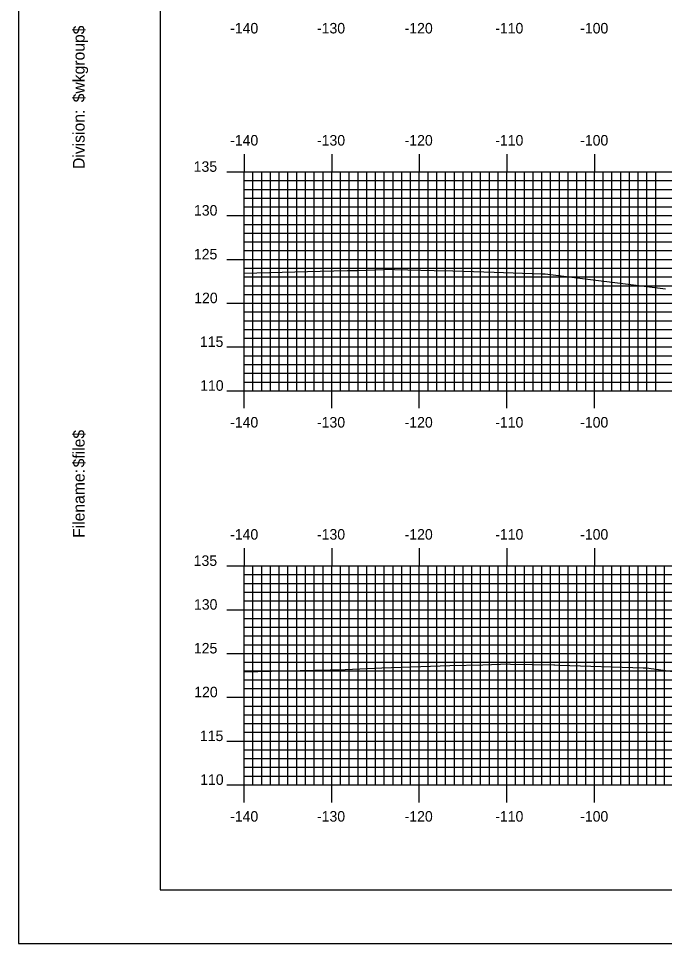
# Model space of a CAD drawing. Extents: x 843356 to 843699, y 363538 to 363758.
# Drawn here: x 843355.6 to 843429.4, y 363537.6 to 363643.2 of the extents above; entities that cross this region are included whole.
import ezdxf

# ---------------------------------------------------------------- set-up
doc = ezdxf.new("R2010")
doc.units = 0
for name, color, linetype in [('BORDER', 7, 'Continuous'), ('H_V ANNOTATION', 7, 'Continuous'), ('M_Roadway_Centerline', 7, 'Continuous'), ('MAJOR', 7, 'Continuous'), ('MINOR', 7, 'Continuous'), ('PLOT BOUNDARY', 7, 'Continuous'), ('S_Roadway_Centerline', 7, 'Continuous')]:
    doc.layers.add(name, color=color, linetype=linetype)

msp = doc.modelspace()

# ---------------------------------------------------------------- linework, layer by layer
at = {"layer": 'BORDER'}
msp.add_lwpolyline([(843371.82, 363543.72), (843691.82, 363543.72), (843691.82, 363753.72), (843371.82, 363753.72)], close=True, dxfattribs=at)
at = {"layer": 'MAJOR'}
for p, q in [((843381.42, 363627.73), (843381.42, 363625.72)), ((843391.42, 363627.73), (843391.42, 363625.72)), ((843401.42, 363627.73), (843401.42, 363625.72)), ((843411.42, 363627.73), (843411.42, 363625.72)), ((843421.42, 363627.73), (843421.42, 363625.72)), ((843379.42, 363625.72), (843381.42, 363625.72)), ((843381.42, 363625.72), (843661.42, 363625.72)), ((843381.42, 363600.72), (843381.42, 363625.72)), ((843381.42, 363600.72), (843381.42, 363625.72)), ((843381.42, 363625.72), (843661.42, 363625.72)), ((843391.42, 363600.72), (843391.42, 363625.72)), ((843401.42, 363600.72), (843401.42, 363625.72)), ((843411.42, 363600.72), (843411.42, 363625.72)), ((843421.42, 363600.72), (843421.42, 363625.72)), ((843379.42, 363620.72), (843381.42, 363620.72)), ((843381.42, 363620.72), (843661.42, 363620.72)), ((843379.42, 363615.72), (843381.42, 363615.72)), ((843381.42, 363615.72), (843661.42, 363615.72)), ((843379.42, 363610.72), (843381.42, 363610.72)), ((843381.42, 363610.72), (843661.42, 363610.72)), ((843379.42, 363605.72), (843381.42, 363605.72)), ((843381.42, 363605.72), (843661.42, 363605.72)), ((843379.42, 363600.72), (843381.42, 363600.72)), ((843381.42, 363600.72), (843661.42, 363600.72)), ((843381.42, 363600.72), (843661.42, 363600.72)), ((843381.42, 363598.72), (843381.42, 363600.72)), ((843391.42, 363598.72), (843391.42, 363600.72)), ((843401.42, 363598.72), (843401.42, 363600.72)), ((843411.42, 363598.72), (843411.42, 363600.72)), ((843421.42, 363598.72), (843421.42, 363600.72)), ((843381.42, 363582.73), (843381.42, 363580.72)), ((843391.42, 363582.73), (843391.42, 363580.72)), ((843401.42, 363582.73), (843401.42, 363580.72)), ((843411.42, 363582.73), (843411.42, 363580.72)), ((843421.42, 363582.73), (843421.42, 363580.72)), ((843379.42, 363580.72), (843381.42, 363580.72)), ((843381.42, 363580.72), (843661.42, 363580.72)), ((843381.42, 363555.72), (843381.42, 363580.72)), ((843381.42, 363555.72), (843381.42, 363580.72)), ((843381.42, 363580.72), (843661.42, 363580.72)), ((843391.42, 363555.72), (843391.42, 363580.72)), ((843401.42, 363555.72), (843401.42, 363580.72)), ((843411.42, 363555.72), (843411.42, 363580.72)), ((843421.42, 363555.72), (843421.42, 363580.72)), ((843379.42, 363575.72), (843381.42, 363575.72)), ((843381.42, 363575.72), (843661.42, 363575.72)), ((843379.42, 363570.72), (843381.42, 363570.72)), ((843381.42, 363570.72), (843661.42, 363570.72)), ((843379.42, 363565.72), (843381.42, 363565.72)), ((843381.42, 363565.72), (843661.42, 363565.72)), ((843379.42, 363560.72), (843381.42, 363560.72)), ((843381.42, 363560.72), (843661.42, 363560.72)), ((843379.42, 363555.72), (843381.42, 363555.72)), ((843381.42, 363555.72), (843661.42, 363555.72)), ((843381.42, 363555.72), (843661.42, 363555.72)), ((843381.42, 363553.72), (843381.42, 363555.72)), ((843391.42, 363553.72), (843391.42, 363555.72)), ((843401.42, 363553.72), (843401.42, 363555.72)), ((843411.42, 363553.72), (843411.42, 363555.72)), ((843421.42, 363553.72), (843421.42, 363555.72))]:
    msp.add_line(p, q, dxfattribs=at)
at = {"layer": 'MINOR'}
for p, q in [((843382.42, 363600.72), (843382.42, 363625.72)), ((843383.42, 363600.72), (843383.42, 363625.72)), ((843384.42, 363600.72), (843384.42, 363625.72)), ((843385.42, 363600.72), (843385.42, 363625.72)), ((843386.42, 363600.72), (843386.42, 363625.72)), ((843387.42, 363600.72), (843387.42, 363625.72)), ((843388.42, 363600.72), (843388.42, 363625.72)), ((843389.42, 363600.72), (843389.42, 363625.72)), ((843390.42, 363600.72), (843390.42, 363625.72)), ((843392.42, 363600.72), (843392.42, 363625.72)), ((843393.42, 363600.72), (843393.42, 363625.72)), ((843394.42, 363600.72), (843394.42, 363625.72)), ((843395.42, 363600.72), (843395.42, 363625.72)), ((843396.42, 363600.72), (843396.42, 363625.72)), ((843397.42, 363600.72), (843397.42, 363625.72)), ((843398.42, 363600.72), (843398.42, 363625.72)), ((843399.42, 363600.72), (843399.42, 363625.72)), ((843400.42, 363600.72), (843400.42, 363625.72)), ((843402.42, 363600.72), (843402.42, 363625.72)), ((843403.42, 363600.72), (843403.42, 363625.72)), ((843404.42, 363600.72), (843404.42, 363625.72)), ((843405.42, 363600.72), (843405.42, 363625.72)), ((843406.42, 363600.72), (843406.42, 363625.72)), ((843407.42, 363600.72), (843407.42, 363625.72)), ((843408.42, 363600.72), (843408.42, 363625.72)), ((843409.42, 363600.72), (843409.42, 363625.72)), ((843410.42, 363600.72), (843410.42, 363625.72)), ((843412.42, 363600.72), (843412.42, 363625.72)), ((843413.42, 363600.72), (843413.42, 363625.72)), ((843414.42, 363600.72), (843414.42, 363625.72)), ((843415.42, 363600.72), (843415.42, 363625.72)), ((843416.42, 363600.72), (843416.42, 363625.72)), ((843417.42, 363600.72), (843417.42, 363625.72)), ((843418.42, 363600.72), (843418.42, 363625.72)), ((843419.42, 363600.72), (843419.42, 363625.72)), ((843420.42, 363600.72), (843420.42, 363625.72)), ((843422.42, 363600.72), (843422.42, 363625.72)), ((843423.42, 363600.72), (843423.42, 363625.72)), ((843424.42, 363600.72), (843424.42, 363625.72)), ((843425.42, 363600.72), (843425.42, 363625.72)), ((843426.42, 363600.72), (843426.42, 363625.72)), ((843427.42, 363600.72), (843427.42, 363625.72)), ((843428.42, 363600.72), (843428.42, 363625.72)), ((843381.42, 363624.72), (843661.42, 363624.72)), ((843381.42, 363624.72), (843383.43, 363624.72)), ((843381.42, 363623.72), (843661.42, 363623.72)), ((843381.42, 363623.72), (843383.43, 363623.72)), ((843381.42, 363622.72), (843661.42, 363622.72)), ((843381.42, 363622.72), (843383.43, 363622.72)), ((843381.42, 363621.72), (843661.42, 363621.72)), ((843381.42, 363621.72), (843383.43, 363621.72)), ((843381.42, 363619.72), (843661.42, 363619.72)), ((843381.42, 363619.72), (843383.43, 363619.72)), ((843381.42, 363618.72), (843661.42, 363618.72)), ((843381.42, 363618.72), (843383.43, 363618.72)), ((843381.42, 363617.72), (843661.42, 363617.72)), ((843381.42, 363617.72), (843383.43, 363617.72)), ((843381.42, 363616.72), (843661.42, 363616.72)), ((843381.42, 363616.72), (843383.43, 363616.72)), ((843381.42, 363614.72), (843661.42, 363614.72)), ((843381.42, 363614.72), (843383.43, 363614.72)), ((843381.42, 363613.72), (843661.42, 363613.72)), ((843381.42, 363613.72), (843383.43, 363613.72)), ((843381.42, 363612.72), (843661.42, 363612.72)), ((843381.42, 363612.72), (843383.43, 363612.72)), ((843381.42, 363611.72), (843661.42, 363611.72)), ((843381.42, 363611.72), (843383.43, 363611.72)), ((843381.42, 363609.72), (843661.42, 363609.72)), ((843381.42, 363609.72), (843383.43, 363609.72)), ((843381.42, 363608.72), (843661.42, 363608.72)), ((843381.42, 363608.72), (843383.43, 363608.72)), ((843381.42, 363607.72), (843661.42, 363607.72)), ((843381.42, 363607.72), (843383.43, 363607.72)), ((843381.42, 363606.72), (843661.42, 363606.72)), ((843381.42, 363606.72), (843383.43, 363606.72)), ((843381.42, 363604.72), (843661.42, 363604.72)), ((843381.42, 363604.72), (843383.43, 363604.72)), ((843381.42, 363603.72), (843661.42, 363603.72)), ((843381.42, 363603.72), (843383.43, 363603.72)), ((843381.42, 363602.72), (843661.42, 363602.72)), ((843381.42, 363602.72), (843383.43, 363602.72)), ((843381.42, 363601.72), (843661.42, 363601.72)), ((843381.42, 363601.72), (843383.43, 363601.72)), ((843382.42, 363555.72), (843382.42, 363580.72)), ((843383.42, 363555.72), (843383.42, 363580.72)), ((843384.42, 363555.72), (843384.42, 363580.72)), ((843385.42, 363555.72), (843385.42, 363580.72)), ((843386.42, 363555.72), (843386.42, 363580.72)), ((843387.42, 363555.72), (843387.42, 363580.72)), ((843388.42, 363555.72), (843388.42, 363580.72)), ((843389.42, 363555.72), (843389.42, 363580.72)), ((843390.42, 363555.72), (843390.42, 363580.72)), ((843392.42, 363555.72), (843392.42, 363580.72)), ((843393.42, 363555.72), (843393.42, 363580.72)), ((843394.42, 363555.72), (843394.42, 363580.72)), ((843395.42, 363555.72), (843395.42, 363580.72)), ((843396.42, 363555.72), (843396.42, 363580.72)), ((843397.42, 363555.72), (843397.42, 363580.72)), ((843398.42, 363555.72), (843398.42, 363580.72)), ((843399.42, 363555.72), (843399.42, 363580.72)), ((843400.42, 363555.72), (843400.42, 363580.72)), ((843402.42, 363555.72), (843402.42, 363580.72)), ((843403.42, 363555.72), (843403.42, 363580.72)), ((843404.42, 363555.72), (843404.42, 363580.72)), ((843405.42, 363555.72), (843405.42, 363580.72)), ((843406.42, 363555.72), (843406.42, 363580.72)), ((843407.42, 363555.72), (843407.42, 363580.72)), ((843408.42, 363555.72), (843408.42, 363580.72)), ((843409.42, 363555.72), (843409.42, 363580.72)), ((843410.42, 363555.72), (843410.42, 363580.72)), ((843412.42, 363555.72), (843412.42, 363580.72)), ((843413.42, 363555.72), (843413.42, 363580.72)), ((843414.42, 363555.72), (843414.42, 363580.72)), ((843415.42, 363555.72), (843415.42, 363580.72)), ((843416.42, 363555.72), (843416.42, 363580.72)), ((843417.42, 363555.72), (843417.42, 363580.72)), ((843418.42, 363555.72), (843418.42, 363580.72)), ((843419.42, 363555.72), (843419.42, 363580.72)), ((843420.42, 363555.72), (843420.42, 363580.72)), ((843422.42, 363555.72), (843422.42, 363580.72)), ((843423.42, 363555.72), (843423.42, 363580.72)), ((843424.42, 363555.72), (843424.42, 363580.72)), ((843425.42, 363555.72), (843425.42, 363580.72)), ((843426.42, 363555.72), (843426.42, 363580.72)), ((843427.42, 363555.72), (843427.42, 363580.72)), ((843428.42, 363555.72), (843428.42, 363580.72)), ((843429.42, 363555.72), (843429.42, 363580.72)), ((843381.42, 363579.72), (843661.42, 363579.72)), ((843381.42, 363579.72), (843383.43, 363579.72)), ((843381.42, 363578.72), (843661.42, 363578.72)), ((843381.42, 363578.72), (843383.43, 363578.72)), ((843381.42, 363577.72), (843661.42, 363577.72)), ((843381.42, 363577.72), (843383.43, 363577.72)), ((843381.42, 363576.72), (843661.42, 363576.72)), ((843381.42, 363576.72), (843383.43, 363576.72)), ((843381.42, 363574.72), (843661.42, 363574.72)), ((843381.42, 363574.72), (843383.43, 363574.72)), ((843381.42, 363573.72), (843661.42, 363573.72)), ((843381.42, 363573.72), (843383.43, 363573.72)), ((843381.42, 363572.72), (843661.42, 363572.72)), ((843381.42, 363572.72), (843383.43, 363572.72)), ((843381.42, 363571.72), (843661.42, 363571.72)), ((843381.42, 363571.72), (843383.43, 363571.72)), ((843381.42, 363569.72), (843661.42, 363569.72)), ((843381.42, 363569.72), (843383.43, 363569.72)), ((843381.42, 363568.72), (843661.42, 363568.72)), ((843381.42, 363568.72), (843383.43, 363568.72)), ((843381.42, 363567.72), (843661.42, 363567.72)), ((843381.42, 363567.72), (843383.43, 363567.72)), ((843381.42, 363566.72), (843661.42, 363566.72)), ((843381.42, 363566.72), (843383.43, 363566.72)), ((843381.42, 363564.72), (843661.42, 363564.72)), ((843381.42, 363564.72), (843383.43, 363564.72)), ((843381.42, 363563.72), (843661.42, 363563.72)), ((843381.42, 363563.72), (843383.43, 363563.72)), ((843381.42, 363562.72), (843661.42, 363562.72)), ((843381.42, 363562.72), (843383.43, 363562.72)), ((843381.42, 363561.72), (843661.42, 363561.72)), ((843381.42, 363561.72), (843383.43, 363561.72)), ((843381.42, 363559.72), (843661.42, 363559.72)), ((843381.42, 363559.72), (843383.43, 363559.72)), ((843381.42, 363558.72), (843661.42, 363558.72)), ((843381.42, 363558.72), (843383.43, 363558.72)), ((843381.42, 363557.72), (843661.42, 363557.72)), ((843381.42, 363557.72), (843383.43, 363557.72)), ((843381.42, 363556.72), (843661.42, 363556.72)), ((843381.42, 363556.72), (843383.43, 363556.72))]:
    msp.add_line(p, q, dxfattribs=at)
at = {"layer": 'PLOT BOUNDARY'}
msp.add_lwpolyline([(843355.64, 363537.6), (843695.64, 363537.6), (843695.64, 363757.6), (843355.64, 363757.6)], close=True, dxfattribs=at)
at = {"layer": 'S_Roadway_Centerline'}
for points in [[(843381.42, 363614.16), (843390.08, 363614.36), (843393.22, 363614.46), (843394.4, 363614.47), (843398.42, 363614.59), (843398.57, 363614.56), (843403.11, 363614.47), (843405.24, 363614.42), (843409.96, 363614.26), (843415.37, 363614.09), (843415.78, 363614.06), (843429.52, 363612.34)], [(843381.42, 363568.63), (843386.1, 363568.74), (843392.95, 363568.88), (843397.14, 363569.07), (843404.91, 363569.35), (843408.68, 363569.43), (843411.68, 363569.53), (843411.85, 363569.5), (843416.79, 363569.41), (843416.9, 363569.41), (843417.44, 363569.39), (843427, 363569.09), (843427.36, 363569.07), (843433.66, 363568.22)]]:
    msp.add_lwpolyline(points, dxfattribs=at)

# ---------------------------------------------------------------- texts
at = {"layer": 'BORDER'}
for s, p in [('$wkgroup$', (843363.19, 363633.66)), ('Division:', (843363.19, 363626.05)), ('$file$', (843363.19, 363591.97)), ('Filename:', (843363.19, 363583.92))]:
    msp.add_text(s, height=1.339, rotation=90, dxfattribs=at).set_placement(p)
at = {"layer": 'H_V ANNOTATION'}
for s, p in [('-140', (843379.81, 363641.52)), ('-130', (843389.73, 363641.52)), ('-120', (843399.74, 363641.52)), ('-110', (843410.09, 363641.52)), ('-100', (843419.79, 363641.52)), ('-140', (843379.81, 363628.72)), ('-130', (843389.73, 363628.72)), ('-120', (843399.74, 363628.72)), ('-110', (843410.09, 363628.72)), ('-100', (843419.79, 363628.72)), ('135', (843375.65, 363625.72)), ('130', (843375.68, 363620.72)), ('125', (843375.67, 363615.72)), ('120', (843375.71, 363610.72)), ('115', (843376.36, 363605.72)), ('110', (843376.39, 363600.72)), ('-140', (843379.81, 363596.52)), ('-130', (843389.73, 363596.52)), ('-120', (843399.74, 363596.52)), ('-110', (843410.09, 363596.52)), ('-100', (843419.79, 363596.52)), ('-140', (843379.81, 363583.72)), ('-130', (843389.73, 363583.72)), ('-120', (843399.74, 363583.72)), ('-110', (843410.09, 363583.72)), ('-100', (843419.79, 363583.72)), ('135', (843375.65, 363580.72)), ('130', (843375.68, 363575.72)), ('125', (843375.67, 363570.72)), ('120', (843375.71, 363565.72)), ('115', (843376.36, 363560.72)), ('110', (843376.39, 363555.72)), ('-140', (843379.81, 363551.52)), ('-130', (843389.73, 363551.52)), ('-120', (843399.74, 363551.52)), ('-110', (843410.09, 363551.52)), ('-100', (843419.79, 363551.52))]:
    msp.add_text(s, height=1.2, dxfattribs=at).set_placement(p)
at = {"layer": 'M_Roadway_Centerline'}
for s, p in [('C', (843411.67, 363569.53)), ('L', (843411.68, 363569.52))]:
    msp.add_text(s, height=0.0146, dxfattribs=at).set_placement(p)
at = {"layer": 'MAJOR'}
for p in [(843381.42, 363600.72), (843381.42, 363555.72)]:
    msp.add_text('-', height=0.012, dxfattribs=at).set_placement(p)

doc.saveas('drawing.dxf')
